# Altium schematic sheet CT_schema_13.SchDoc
size 147 x 119 mm
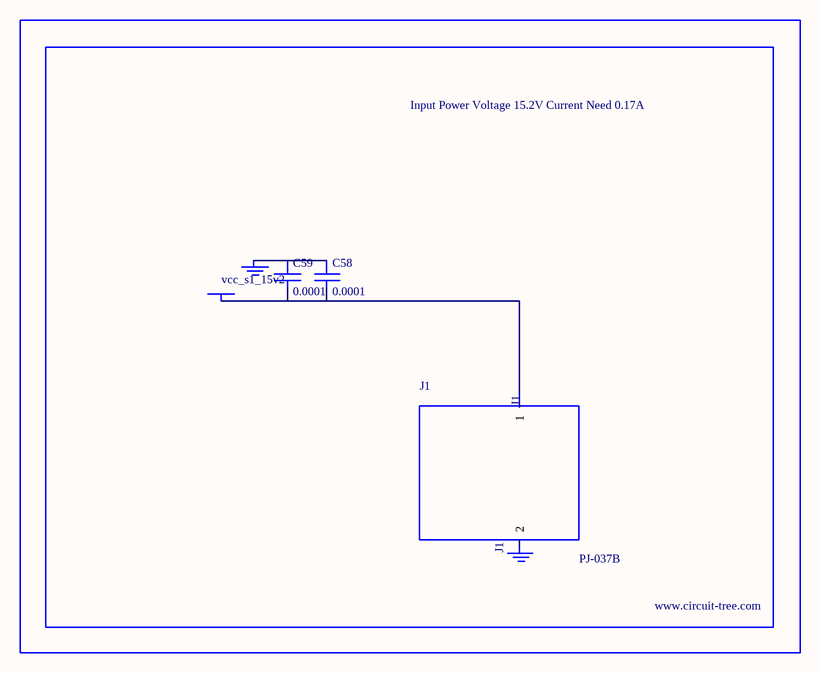
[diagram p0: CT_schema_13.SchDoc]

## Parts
BORDER12  (no value)
C58  0.0001  [EXV-9H]
C59  0.0001  [EXV-9H]
GND_INSTANCE_12_0  (no value)
GND_INSTANCE_12_1  (no value)
J1  PJ-037B  [PJ-037B_PACKAGE]
POWER_INSTANCE_12_0  vcc_s1_15v2

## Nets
NetC58_1: C58.1 C59.1 GND_INSTANCE_12_0.0(GND)
NetC58_2: C58.2 C59.2 J1.1 POWER_INSTANCE_12_0.0(PWR)

Not connected (* = marked no-connect by the designer): GND_INSTANCE_12_1 0(GND); J1 2

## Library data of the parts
BORDER12 = BORDER_PAGE12
C58 C59 = EDK107M035A9HAA
GND_INSTANCE_12_0 GND_INSTANCE_12_1 = GND
POWER_INSTANCE_12_0 = PWR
